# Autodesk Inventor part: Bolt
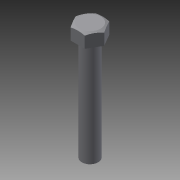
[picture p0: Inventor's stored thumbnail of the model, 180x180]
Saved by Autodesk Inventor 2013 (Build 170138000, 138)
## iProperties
Created: 2004-07
Part Number: Bolt
Document SubType Name: Modeling
Designer: Autodesk, Inc.
Manufacturer: Standard
Standards Organization: Custom
Density: 1 g/cm^3
Mass: 21.9731 g
Surface Area: 62.2533 cm^2
Volume: 21.9731 cm^3
Material: Generic
Author: Autodesk, Inc.
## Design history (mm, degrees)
sketch "Sketch1"
  geometry: L1 (-12.99, 0)-(-6.495, 11.25); L2 (-6.495, 11.25)-(6.495, 11.25); L3 (6.495, 11.25)-(12.99, 0); L4 (12.99, 0)-(6.495, -11.25); L5 (6.495, -11.25)-(-6.495, -11.25); L6 (-6.495, -11.25)-(-12.99, 0); 2 further points
  constraints: 12 end point, 1 coincident, 11 other
  dimensions: "Bolt_Width" = 22.5 distance between parallel lines of L5 L2 (= 1.5 x Bolt_Diameter)
extrude "Extrusion1" new body sketch "Sketch1" taper "d2" = 0 deg; distance "Bolt_Height" = 12
sketch "Sketch2"
  geometry: L1 (0, -2.6)-(0, 15.6) reference; L2 (13.8, 13)-(13.8, 10); L3 (13.8, 10)-(7.8, 13); L4 (7.8, 13)-(13.8, 13); L5 (12.99, 0)-(6.495, 0) reference; L6 (6.495, 0)-(-6.495, 0) reference; L7 (-6.495, 0)-(-12.99, 0) reference; L8 (-12.99, 0)-(-6.495, 0) reference; L9 (-6.495, 0)-(6.495, 0) reference; L10 (6.495, 0)-(12.99, 0) reference
  constraints: 6 end point, 1 parallel, 1 perpendicular
  dimensions: "d3" = 27.6 diameter of L2 L1; "d4" = 3 distance of L2.start L2.end; "d5" = 13 distance between parallel lines of L4 L5; "d6" = 6 distance of L3.end L2.start
revolve "Revolution1" sketch "Sketch2" stored, may be unused: angle "d7" = 90 deg
sketch "Sketch3"
  geometry: C1 r 7.5 at (0, 0); 1 further point
  constraints: 1 centre point, 1 coincident
  dimensions: "Bolt_Diameter" = 15 diameter of C1
extrude "Extrusion2" join sketch "Sketch3" taper "d10" = 0 deg; distance "Bolt_Length" = 95
body "Solid1"
node "Projected Loop1"
